Omron CX-Programmer project NewProject (CX-Programmer 9.20)

# PLC NewPLC1: CJ1M CPU11
I/O table (CPU CJ1M-CPU11): rack 0 slot 0 CJ1W-ETN21(ETN21Mode); rack 0 slot 1 CJ1W-ID211; rack 0 slot 2 CJ1W-OC211

## Global symbols (name address type ; comment)
A202.00 BOOL  ; Communications Port #0 Enabled Flag
Data_Recv_Area_Start W450 UINT
Data_Send_Area_Start W400 UINT
Send_Data1_C D3000 CHANNEL  ; Number Of Words
Send_Data1_C1 D3001 CHANNEL  ; $?St$Bk?_#[23] / MSB - Fixed #0 for First Number / MSB - Serial Port Number for Second Number #0 Not Used / LSB - Network Address$?St$Bk?_#[23]
Send_Data1_C2 D3002 CHANNEL  ; $?St$Bk?_#[24] / MSB - Node Address / LSB - Unit Address$?St$Bk?_#[24]
Send_Data1_C3 D3003 CHANNEL  ; $?St$Bk?_#[25] / MSB - Response Needed / Not Needed for First Number #0 Needed / MSB - Logical Port Number for Second Number / LSB - Fixed for Third Number / LSB - Resend Times for Fourth Numberf$?St$Bk?_#[25]
Send_Data1_C4 D3004 CHANNEL  ; Response Monitor Time (#0000 = 2 Seconds for Default Value)

## Program NewProgram1 (cyclic task 0)

### Section Section1

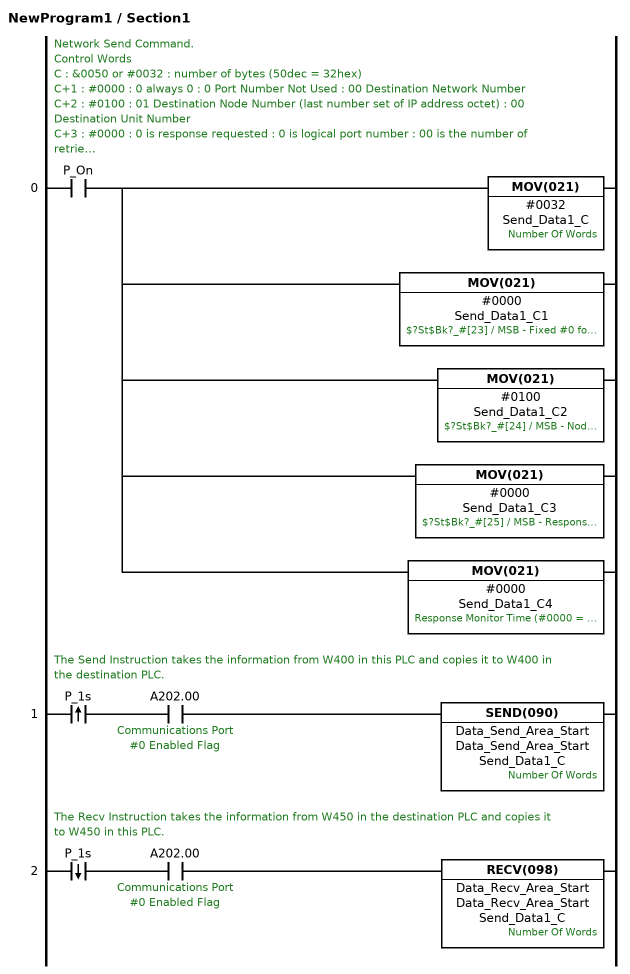
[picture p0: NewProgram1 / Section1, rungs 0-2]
; rung 0: Network Send Command. / Control Words / C : &0050 or #0032 : number of bytes (50dec = 32hex) / C+1 : #0000 : 0 always 0 : 0 Port Number Not Used : 00 Destination Network Number / C+2 : #0100 : 01 Destination Node Number (last number set of IP address octet) : 00 Destination Unit Number / C+3 : #0000 : 0 is response requested : 0 is logical port number : 00 is the number of retries / C+4 : #0000 : 0000 response time out default 2 seconds
LD P_On
MOV(021) #0032 Send_Data1_C  ; Number Of Words
MOV(021) #0000 Send_Data1_C1  ; $?St$Bk?_#[23] / MSB - Fixed #0 for First Number / MSB - Serial Port Number for Second Number #0 Not Used / LSB - Network Address$?St$Bk?_#[23]
MOV(021) #0100 Send_Data1_C2  ; $?St$Bk?_#[24] / MSB - Node Address / LSB - Unit Address$?St$Bk?_#[24]
MOV(021) #0000 Send_Data1_C3  ; $?St$Bk?_#[25] / MSB - Response Needed / Not Needed for First Number #0 Needed / MSB - Logical Port Number for Second Number / LSB - Fixed for Third Number / LSB - Resend Times for Fourth Numberf$?St$Bk?_#[25]
MOV(021) #0000 Send_Data1_C4  ; Response Monitor Time (#0000 = 2 Seconds for Default Value)
; rung 1: The Send Instruction takes the information from W400 in this PLC and copies it to W400 in the destination PLC.
@LD P_1s
AND A202.00  ; Communications Port #0 Enabled Flag
SEND(090) Data_Send_Area_Start Data_Send_Area_Start Send_Data1_C  ; Number Of Words
; rung 2: The Recv Instruction takes the information from W450 in the destination PLC and copies it to W450 in this PLC.
%LD P_1s
AND A202.00  ; Communications Port #0 Enabled Flag
RECV(098) Data_Recv_Area_Start Data_Recv_Area_Start Send_Data1_C  ; Number Of Words

### Section END
; rung 0
END(001)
